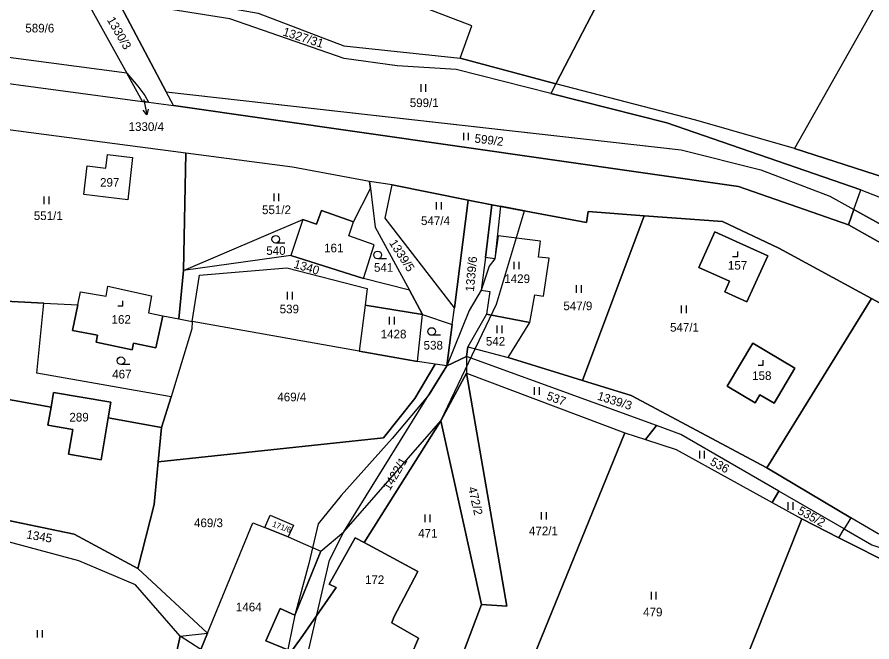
# Model space of a CAD drawing. Extents: x -588699 to -585793, y -1060280 to -1056731.
# Drawn here: x -586828.9 to -586660.9, y -1058673.3 to -1058550.5 of the extents above; entities that cross this region are included whole.
import ezdxf

# ---------------------------------------------------------------- set-up
doc = ezdxf.new("R2010")
doc.units = 0
for name, color, linetype in [('Druh pozemku', 7, 'Continuous'), ('Lesy', 7, 'Continuous'), ('Parcela nároku', 7, 'Continuous'), ('Parcelní číslo', 7, 'Continuous')]:
    doc.layers.add(name, color=color, linetype=linetype)

msp = doc.modelspace()

# ---------------------------------------------------------------- linework, layer by layer
at = {"layer": 'Druh pozemku'}
for p, q in [((-586749.55, -1058563.65), (-586749.55, -1058565.15)), ((-586748.53, -1058565.15), (-586748.53, -1058563.65)), ((-586741.18, -1058573.21), (-586741.18, -1058574.71)), ((-586740.16, -1058574.71), (-586740.16, -1058573.21)), ((-586778.45, -1058585.15), (-586778.45, -1058586.65)), ((-586777.43, -1058586.65), (-586777.43, -1058585.15)), ((-586823.62, -1058585.77), (-586823.62, -1058587.27)), ((-586822.59, -1058587.27), (-586822.59, -1058585.77)), ((-586746.52, -1058586.84), (-586746.52, -1058588.34)), ((-586745.49, -1058588.34), (-586745.49, -1058586.84)), ((-586776.29, -1058594.9), (-586778.04, -1058594.9)), ((-586756.27, -1058598), (-586758.02, -1058598)), ((-586731.24, -1058598.57), (-586731.24, -1058600.07)), ((-586730.21, -1058600.07), (-586730.21, -1058598.57)), ((-586719, -1058603.18), (-586719, -1058604.68)), ((-586717.97, -1058604.68), (-586717.97, -1058603.18)), ((-586775.81, -1058604.48), (-586775.81, -1058605.98)), ((-586774.79, -1058605.98), (-586774.79, -1058604.48)), ((-586698.37, -1058607.21), (-586698.37, -1058608.71)), ((-586697.34, -1058608.71), (-586697.34, -1058607.21)), ((-586755.75, -1058609.4), (-586755.75, -1058610.9)), ((-586754.72, -1058610.9), (-586754.72, -1058609.4)), ((-586734.62, -1058611.12), (-586734.62, -1058612.62)), ((-586733.59, -1058612.62), (-586733.59, -1058611.12)), ((-586745.65, -1058613.04), (-586747.4, -1058613.04)), ((-586806.72, -1058618.79), (-586808.47, -1058618.79)), ((-586727.26, -1058623.23), (-586727.26, -1058624.73)), ((-586726.23, -1058624.73), (-586726.23, -1058623.23)), ((-586694.82, -1058635.75), (-586694.82, -1058637.25)), ((-586693.8, -1058637.25), (-586693.8, -1058635.75)), ((-586677.44, -1058645.85), (-586677.44, -1058647.35)), ((-586676.42, -1058647.35), (-586676.42, -1058645.85)), ((-586748.76, -1058648.25), (-586748.76, -1058649.75)), ((-586747.73, -1058649.75), (-586747.73, -1058648.25)), ((-586725.87, -1058647.77), (-586725.87, -1058649.27)), ((-586724.84, -1058649.27), (-586724.84, -1058647.77)), ((-586704.3, -1058663.47), (-586704.3, -1058664.97)), ((-586703.28, -1058664.97), (-586703.28, -1058663.47)), ((-586824.9, -1058670.96), (-586824.9, -1058672.46)), ((-586823.88, -1058672.46), (-586823.88, -1058670.96))]:
    msp.add_line(p, q, dxfattribs=at)
for points in [[(-586688.29, -1058597.57), (-586687.29, -1058597.57), (-586687.29, -1058596.57)], [(-586809.11, -1058607.26), (-586808.11, -1058607.26), (-586808.11, -1058606.26)], [(-586683.27, -1058618.91), (-586682.27, -1058618.91), (-586682.27, -1058617.91)]]:
    msp.add_lwpolyline(points, dxfattribs=at)
for centre in [(-586778.04, -1058594.15), (-586758.02, -1058597.25), (-586747.4, -1058612.29), (-586808.47, -1058618.04)]:
    msp.add_circle(centre, 0.75, dxfattribs=at)
at = {"layer": 'Lesy'}
for p, q in [((-586808.99, -1058547.38), (-586799.56, -1058565.21)), ((-586799.56, -1058565.21), (-586748.98, -1058570.88)), ((-586748.98, -1058570.88), (-586698.41, -1058576.55)), ((-586698.41, -1058576.55), (-586682.76, -1058580.5)), ((-586682.76, -1058580.5), (-586669.18, -1058585.71)), ((-586669.18, -1058585.71), (-586664.46, -1058588.32)), ((-586664.46, -1058588.32), (-586623.04, -1058611.28)), ((-586817.65, -1058652.11), (-586851.48, -1058645.09)), ((-586674.68, -1058649.14), (-586694.07, -1058697.8)), ((-586667.41, -1058652.83), (-586674.68, -1058649.14)), ((-586805.15, -1058658.88), (-586817.65, -1058652.11)), ((-586656.24, -1058658.5), (-586667.41, -1058652.83)), ((-586791.48, -1058671.6), (-586805.15, -1058658.88)), ((-586799.98, -1058686.35), (-586796.81, -1058672.17)), ((-586796.81, -1058672.17), (-586791.48, -1058671.6))]:
    msp.add_line(p, q, dxfattribs=at)
msp.add_lwpolyline([(-586768.32, -1058678.54), (-586772.18, -1058677.61), (-586767.47, -1058657.22), (-586764.67, -1058651.64), (-586745.61, -1058629.88), (-586734.69, -1058606.92), (-586729.15, -1058588.58), (-586733.92, -1058587.68), (-586735.03, -1058597.99), (-586736.15, -1058599.47), (-586737.67, -1058604.17), (-586740.08, -1058608.18), (-586744.45, -1058619.04), (-586747.94, -1058624.66), (-586755.17, -1058633.29), (-586765.18, -1058644.52), (-586769.72, -1058650.09), (-586771.54, -1058657.92), (-586774.3, -1058668.05), (-586776.04, -1058676.69)], dxfattribs=at)
at = {"layer": 'Parcela nároku'}
for points in [[(-586465.07, -1058201.01), (-586462.81, -1058212.17), (-586445.25, -1058224.99), (-586469.35, -1058367.39), (-586494.03, -1058434.82), (-586515.59, -1058473.49), (-586537.48, -1058501.65), (-586550.1, -1058524), (-586565.09, -1058560.52), (-586647.87, -1058526.28), (-586676.13, -1058576.31), (-586695.54, -1058570.75), (-586723.01, -1058563.64), (-586690.86, -1058501.66), (-586638.81, -1058427.57), (-586625.18, -1058408.12), (-586613.79, -1058336.04), (-586618.19, -1058334.15), (-586615.1, -1058282.91), (-586614.12, -1058226.2), (-586599.85, -1058168.12)], [(-586934.89, -1058550.47), (-586933.62, -1058550.62), (-586874.68, -1058557.5), (-586872.37, -1058557.77), (-586854.02, -1058560.42), (-586804.23, -1058567.06), (-586803.05, -1058567.22), (-586798.16, -1058567.87), (-586687.14, -1058583.77), (-586665.54, -1058591.33), (-586602.99, -1058626.52)], [(-586618.94, -1058628.76), (-586660.99, -1058605.82), (-586679.22, -1058595.88), (-586690.29, -1058590.65), (-586705.65, -1058589.53), (-586716.68, -1058588.73), (-586716.99, -1058590.88), (-586735.61, -1058587.36), (-586740.23, -1058586.48), (-586755.16, -1058583.44), (-586759.61, -1058582.79), (-586774.79, -1058579.98), (-586795.7, -1058577.24), (-586856.59, -1058569.23), (-586909.75, -1058563.5), (-586913.94, -1058563.18), (-586935.4, -1058561.66), (-586937.84, -1058561.49), (-586942.57, -1058559.22), (-586946.78, -1058558.67)]]:
    msp.add_lwpolyline(points, dxfattribs=at)
for points in [[(-586698.57, -1058489.96), (-586674.92, -1058458.59), (-586651.91, -1058406.23), (-586620.38, -1058345.44), (-586618.19, -1058334.15), (-586613.79, -1058336.04), (-586625.18, -1058408.12), (-586638.81, -1058427.57), (-586690.86, -1058501.66), (-586723.01, -1058563.64), (-586741.83, -1058558.55), (-586739.53, -1058552.23), (-586753.05, -1058547), (-586757.7, -1058536.93), (-586767.21, -1058533.45), (-586771.86, -1058528.97), (-586755.85, -1058518.91), (-586720.86, -1058504.44)], [(-586799.85, -1058517.84), (-586802.95, -1058516.52), (-586804.09, -1058518.34), (-586814.11, -1058543.89), (-586781.49, -1058549.72), (-586764.67, -1058556.16), (-586741.83, -1058558.55), (-586739.53, -1058552.23), (-586753.05, -1058547), (-586757.7, -1058536.93), (-586767.21, -1058533.45), (-586771.86, -1058528.97), (-586775.6, -1058527.48)], [(-586871.4, -1058523.77), (-586875.35, -1058522.58), (-586869.14, -1058528.69), (-586874.19, -1058555.03), (-586862.54, -1058558.15), (-586854.02, -1058560.42), (-586804.23, -1058567.06), (-586807.28, -1058561.54), (-586832.56, -1058558.16), (-586845.52, -1058535.63), (-586863.45, -1058526.16)], [(-586565.09, -1058560.52), (-586647.87, -1058526.28), (-586676.13, -1058576.31), (-586614.58, -1058596.16), (-586607.11, -1058582.84), (-586599.58, -1058574.41), (-586596, -1058567.96), (-586573.24, -1058583.2)], [(-586845.52, -1058535.63), (-586838.02, -1058539.59), (-586814.5, -1058548.51), (-586807.28, -1058561.54), (-586832.56, -1058558.16)], [(-586814.11, -1058543.89), (-586781.49, -1058549.72), (-586764.67, -1058556.16), (-586741.83, -1058558.55), (-586723.01, -1058563.64), (-586723.97, -1058565.5), (-586742.59, -1058560.8), (-586754.19, -1058560.06), (-586764.62, -1058558.63), (-586787.05, -1058550.85), (-586808.99, -1058547.38)], [(-586799.56, -1058565.21), (-586808.99, -1058547.38), (-586814.5, -1058548.51), (-586807.28, -1058561.54), (-586805.12, -1058564.07), (-586803.77, -1058565.9), (-586803.05, -1058567.22), (-586798.16, -1058567.87)], [(-586764.62, -1058558.63), (-586787.05, -1058550.85), (-586808.99, -1058547.38), (-586799.56, -1058565.21), (-586698.41, -1058576.55), (-586682.76, -1058580.5), (-586669.18, -1058585.71), (-586664.46, -1058588.32), (-586663.07, -1058584.46), (-586701.18, -1058571.25), (-586723.97, -1058565.5), (-586742.59, -1058560.8), (-586754.19, -1058560.06)], [(-586807.28, -1058561.54), (-586805.12, -1058564.07), (-586803.77, -1058565.9), (-586803.05, -1058567.22), (-586804.23, -1058567.06)], [(-586695.54, -1058570.75), (-586723.01, -1058563.64), (-586723.97, -1058565.5), (-586701.18, -1058571.25), (-586663.07, -1058584.46), (-586649.29, -1058589.84), (-586616.31, -1058599.2), (-586600.16, -1058603.78), (-586584.46, -1058609.63), (-586574.88, -1058615.69), (-586569.97, -1058617.96), (-586565.57, -1058620.73), (-586521.47, -1058658.28), (-586520.5, -1058656.37), (-586561.85, -1058620.29), (-586566.13, -1058616.55), (-586566.86, -1058616.12), (-586567.54, -1058615.71), (-586570.85, -1058613.91), (-586582.12, -1058607.98), (-586593.62, -1058603.21), (-586614.58, -1058596.16), (-586676.13, -1058576.31)], [(-586669.18, -1058585.71), (-586664.46, -1058588.32), (-586665.54, -1058591.33), (-586687.14, -1058583.77), (-586798.16, -1058567.87), (-586799.56, -1058565.21), (-586698.41, -1058576.55), (-586682.76, -1058580.5)], [(-586848.05, -1058580.18), (-586854.38, -1058597.45), (-586849.98, -1058605.33), (-586823.61, -1058606.72), (-586816.91, -1058607.07), (-586816.4, -1058604.52), (-586811.36, -1058605.37), (-586811.07, -1058603.41), (-586802.46, -1058605.29), (-586803.06, -1058608.62), (-586800.23, -1058609.18), (-586797.12, -1058609.8), (-586796.17, -1058600.31), (-586795.7, -1058577.24), (-586856.59, -1058569.23), (-586845.36, -1058572.84)], [(-586806.18, -1058578.11), (-586807.14, -1058586.4), (-586815.79, -1058585.39), (-586815.13, -1058579.72), (-586811.45, -1058580.16), (-586811.13, -1058577.53)], [(-586815.13, -1058579.72), (-586811.45, -1058580.16), (-586811.13, -1058577.53), (-586806.18, -1058578.11), (-586807.14, -1058586.4), (-586815.79, -1058585.39)], [(-586759.61, -1058582.79), (-586774.79, -1058579.98), (-586795.7, -1058577.24), (-586796.17, -1058600.31), (-586772.71, -1058590.27), (-586770.05, -1058591.21), (-586769.05, -1058588.48), (-586762.75, -1058590.71), (-586759.45, -1058584.16)], [(-586755.16, -1058583.44), (-586759.61, -1058582.79), (-586759.45, -1058584.16), (-586758.54, -1058591.77), (-586751.79, -1058604.19), (-586749.19, -1058608.98), (-586743.37, -1058610.94), (-586742.95, -1058607.64), (-586756.53, -1058590.02)], [(-586756.53, -1058590.02), (-586755.16, -1058583.44), (-586740.23, -1058586.48), (-586742.95, -1058607.64)], [(-586760.82, -1058601.89), (-586758.69, -1058595.23), (-586763.68, -1058593.46), (-586762.75, -1058590.71), (-586759.45, -1058584.16), (-586758.54, -1058591.77), (-586751.79, -1058604.19)], [(-586649.29, -1058589.84), (-586616.31, -1058599.2), (-586623.04, -1058611.28), (-586664.46, -1058588.32), (-586663.07, -1058584.46)], [(-586742.95, -1058607.64), (-586740.23, -1058586.48), (-586735.61, -1058587.36), (-586736.87, -1058597.72), (-586737.67, -1058604.17), (-586735.99, -1058604.42), (-586736.65, -1058608.87), (-586740.28, -1058615.3), (-586740.58, -1058617.2), (-586744.45, -1058619.04), (-586743.37, -1058610.94)], [(-586769.05, -1058588.48), (-586770.05, -1058591.21), (-586772.71, -1058590.27), (-586775.09, -1058597.32), (-586760.82, -1058601.89), (-586758.69, -1058595.23), (-586763.68, -1058593.46), (-586762.75, -1058590.71)], [(-586725.43, -1058605.36), (-586724.33, -1058597.89), (-586726.41, -1058597.67), (-586726.04, -1058594.56), (-586734.37, -1058593.49), (-586735.03, -1058597.99), (-586736.87, -1058597.72), (-586735.61, -1058587.36), (-586716.99, -1058590.88), (-586716.68, -1058588.73), (-586705.65, -1058589.53), (-586717.75, -1058621.93), (-586732.41, -1058617.37), (-586728.1, -1058610.55), (-586727.15, -1058605.11)], [(-586597.95, -1058625.16), (-586584.01, -1058632.77), (-586561.96, -1058648.55), (-586562.62, -1058649.44), (-586575.18, -1058640.72), (-586602.99, -1058626.52), (-586665.54, -1058591.33), (-586664.46, -1058588.32), (-586623.04, -1058611.28), (-586607.59, -1058619.84), (-586605.96, -1058620.74), (-586600.89, -1058623.54)], [(-586796.17, -1058600.31), (-586772.71, -1058590.27), (-586775.09, -1058597.32)], [(-586690.29, -1058590.65), (-586679.22, -1058595.88), (-586660.99, -1058605.82), (-586681.54, -1058639.09), (-586708.24, -1058624.88), (-586717.75, -1058621.93), (-586705.65, -1058589.53)], [(-586735.03, -1058597.99), (-586736.87, -1058597.72), (-586737.67, -1058604.17), (-586735.99, -1058604.42), (-586736.65, -1058608.87), (-586728.1, -1058610.55), (-586727.15, -1058605.11), (-586725.43, -1058605.36), (-586724.33, -1058597.89), (-586726.41, -1058597.67), (-586726.04, -1058594.56), (-586734.37, -1058593.49)], [(-586689.84, -1058604.5), (-586688.89, -1058602.39), (-586694.92, -1058599.68), (-586691.79, -1058592.73), (-586681.39, -1058597.39), (-586685.48, -1058606.46)], [(-586694.92, -1058599.68), (-586688.89, -1058602.39), (-586689.84, -1058604.5), (-586685.48, -1058606.46), (-586681.39, -1058597.39), (-586691.79, -1058592.73)], [(-586775.09, -1058597.32), (-586796.17, -1058600.31), (-586797.12, -1058609.8), (-586794.44, -1058610.33), (-586793.06, -1058601.19), (-586775.86, -1058599.8), (-586760.09, -1058603.85), (-586760.51, -1058607.14), (-586749.19, -1058608.98), (-586751.79, -1058604.19), (-586760.82, -1058601.89)], [(-586793.06, -1058601.19), (-586775.86, -1058599.8), (-586760.09, -1058603.85), (-586760.51, -1058607.14), (-586761.66, -1058616.17), (-586794.44, -1058610.33)], [(-586811.36, -1058605.37), (-586811.07, -1058603.41), (-586802.46, -1058605.29), (-586803.06, -1058608.62), (-586800.23, -1058609.18), (-586801.59, -1058615.49), (-586805.98, -1058614.57), (-586806.25, -1058615.92), (-586813.35, -1058614.38), (-586813.07, -1058613.02), (-586817.98, -1058612.11), (-586816.91, -1058607.07), (-586816.4, -1058604.52)], [(-586823.61, -1058606.72), (-586849.98, -1058605.33), (-586851.42, -1058615.61), (-586851.29, -1058621.89), (-586822.19, -1058627.19), (-586821.69, -1058624.31), (-586810.47, -1058626.19), (-586810.97, -1058629.24), (-586800.47, -1058631.15), (-586798.62, -1058625.12), (-586825.01, -1058620.48)], [(-586797.12, -1058609.8), (-586794.44, -1058610.33), (-586794.51, -1058611.77), (-586798.62, -1058625.12), (-586825.01, -1058620.48), (-586823.61, -1058606.72), (-586816.91, -1058607.07), (-586817.98, -1058612.11), (-586813.07, -1058613.02), (-586813.35, -1058614.38), (-586806.25, -1058615.92), (-586805.98, -1058614.57), (-586801.59, -1058615.49), (-586800.23, -1058609.18)], [(-586760.51, -1058607.14), (-586761.66, -1058616.17), (-586750.18, -1058618.21), (-586749.19, -1058608.98)], [(-586681.54, -1058639.09), (-586660.99, -1058605.82), (-586618.94, -1058628.76), (-586637.88, -1058658.21), (-586659.72, -1058652.09), (-586665.04, -1058648.92)], [(-586750.18, -1058618.21), (-586749.19, -1058608.98), (-586743.37, -1058610.94), (-586744.45, -1058619.04), (-586746.74, -1058618.71)], [(-586736.65, -1058608.87), (-586740.28, -1058615.3), (-586732.41, -1058617.37), (-586728.1, -1058610.55)], [(-586746.74, -1058618.71), (-586750.18, -1058618.21), (-586761.66, -1058616.17), (-586794.44, -1058610.33), (-586794.51, -1058611.77), (-586798.62, -1058625.12), (-586800.47, -1058631.15), (-586801.14, -1058637.92), (-586756.88, -1058633.16), (-586750.74, -1058625.45)], [(-586681.54, -1058639.09), (-586665.04, -1058648.92), (-586666.36, -1058651.1), (-586679.21, -1058643.65), (-586698.43, -1058632.52), (-586703.25, -1058630.77), (-586740.58, -1058617.2), (-586740.28, -1058615.3), (-586732.41, -1058617.37), (-586717.75, -1058621.93), (-586708.24, -1058624.88)], [(-586689.33, -1058623.05), (-586684.33, -1058614.61), (-586676.03, -1058619.48), (-586680.12, -1058626.38), (-586682.92, -1058624.73), (-586683.85, -1058626.3)], [(-586680.12, -1058626.38), (-586676.03, -1058619.48), (-586684.33, -1058614.61), (-586689.33, -1058623.05), (-586683.85, -1058626.3), (-586682.92, -1058624.73)], [(-586740.58, -1058617.2), (-586740.56, -1058620.49), (-586745.61, -1058629.88), (-586760.71, -1058653.77), (-586762.47, -1058652.82), (-586767.54, -1058661.93), (-586766.21, -1058662.62), (-586772.73, -1058672.04), (-586776.04, -1058676.69), (-586775.34, -1058674.97), (-586779.97, -1058673.07), (-586777.15, -1058666.75), (-586774.3, -1058668.05), (-586769.19, -1058655.47), (-586764.67, -1058651.64), (-586744.45, -1058619.04)], [(-586703.25, -1058630.77), (-586740.58, -1058617.2), (-586740.56, -1058620.49), (-586709.46, -1058632.19), (-586705.4, -1058633.51)], [(-586750.74, -1058625.45), (-586756.88, -1058633.16), (-586801.14, -1058637.92), (-586801.97, -1058646.29), (-586805.15, -1058658.88), (-586791.48, -1058671.6), (-586782.58, -1058649.89), (-586780.19, -1058650.83), (-586779.13, -1058648.42), (-586774.55, -1058650.35), (-586775.59, -1058652.67), (-586772.21, -1058654.14), (-586769.19, -1058655.47), (-586764.67, -1058651.64), (-586744.45, -1058619.04), (-586746.74, -1058618.71)], [(-586745.61, -1058629.88), (-586740.56, -1058620.49), (-586732.66, -1058666.25), (-586737.6, -1058665.97)], [(-586744.08, -1058683.08), (-586737.6, -1058665.97), (-586732.66, -1058666.25), (-586740.56, -1058620.49), (-586709.46, -1058632.19), (-586731.52, -1058686.37)], [(-586822.19, -1058627.19), (-586851.29, -1058621.89), (-586851.01, -1058642.14), (-586851.48, -1058645.09), (-586817.65, -1058652.11), (-586805.15, -1058658.88), (-586801.97, -1058646.29), (-586801.14, -1058637.92), (-586800.47, -1058631.15), (-586810.97, -1058629.24), (-586812.33, -1058637.49), (-586818.79, -1058636.38), (-586817.95, -1058631.53), (-586822.8, -1058630.72)], [(-586822.19, -1058627.19), (-586822.8, -1058630.72), (-586817.95, -1058631.53), (-586818.79, -1058636.38), (-586812.33, -1058637.49), (-586810.97, -1058629.24), (-586810.47, -1058626.19), (-586821.69, -1058624.31)], [(-586760.71, -1058653.77), (-586745.61, -1058629.88), (-586737.6, -1058665.97), (-586744.08, -1058683.08), (-586754.43, -1058685.69), (-586762.04, -1058681.65), (-586761.21, -1058680.01), (-586754.5, -1058683.18), (-586750, -1058672.54), (-586755.27, -1058669.57), (-586754.82, -1058668.46), (-586750.12, -1058659.46)], [(-586703.25, -1058630.77), (-586705.4, -1058633.51), (-586699.35, -1058635.49), (-586680.49, -1058645.92), (-586679.21, -1058643.65), (-586698.43, -1058632.52)], [(-586705.4, -1058633.51), (-586699.35, -1058635.49), (-586680.49, -1058645.92), (-586674.68, -1058649.14), (-586694.07, -1058697.8), (-586731.52, -1058686.37), (-586709.46, -1058632.19)], [(-586666.36, -1058651.1), (-586679.21, -1058643.65), (-586680.49, -1058645.92), (-586674.68, -1058649.14), (-586667.41, -1058652.83)], [(-586851.48, -1058645.09), (-586817.65, -1058652.11), (-586805.15, -1058658.88), (-586791.48, -1058671.6), (-586792.77, -1058674.76), (-586796.81, -1058672.17), (-586805.63, -1058662.11), (-586816.72, -1058657.34), (-586840.89, -1058650.86), (-586852.11, -1058648.46)], [(-586780.19, -1058650.83), (-586779.13, -1058648.42), (-586774.55, -1058650.35), (-586775.59, -1058652.67)], [(-586656.24, -1058658.5), (-586648.82, -1058664.43), (-586635.45, -1058676.95), (-586627.51, -1058684.38), (-586620.49, -1058689.29), (-586605.29, -1058703.42), (-586575.6, -1058727.47), (-586587.34, -1058735.8), (-586608.24, -1058752.75), (-586626.83, -1058736.19), (-586643.18, -1058723.44), (-586668.27, -1058711.07), (-586694.07, -1058697.8), (-586674.68, -1058649.14), (-586667.41, -1058652.83)], [(-586665.04, -1058648.92), (-586666.36, -1058651.1), (-586660.95, -1058654.23), (-586636.48, -1058662.22), (-586632.69, -1058670.06), (-586632.17, -1058672.66), (-586629.39, -1058669.03), (-586637.88, -1058658.21), (-586659.72, -1058652.09)], [(-586805.63, -1058662.11), (-586816.72, -1058657.34), (-586840.89, -1058650.86), (-586854.39, -1058683.44), (-586852.02, -1058685.29), (-586820.88, -1058699.32), (-586805.39, -1058705.78), (-586803.87, -1058706.44), (-586802.96, -1058699.63), (-586799.98, -1058686.35), (-586796.81, -1058672.17)], [(-586772.21, -1058654.14), (-586769.19, -1058655.47), (-586774.3, -1058668.05), (-586777.15, -1058666.75), (-586779.97, -1058673.07), (-586775.34, -1058674.97), (-586776.04, -1058676.69), (-586776.99, -1058679.01), (-586777.74, -1058680.85), (-586792.77, -1058674.76), (-586791.48, -1058671.6), (-586782.58, -1058649.89), (-586780.19, -1058650.83), (-586775.59, -1058652.67)], [(-586632.69, -1058670.06), (-586632.17, -1058672.66), (-586635.45, -1058676.95), (-586648.82, -1058664.43), (-586656.24, -1058658.5), (-586667.41, -1058652.83), (-586666.36, -1058651.1), (-586660.95, -1058654.23), (-586636.48, -1058662.22)], [(-586767.54, -1058661.93), (-586762.47, -1058652.82), (-586760.71, -1058653.77), (-586750.12, -1058659.46), (-586754.82, -1058668.46), (-586755.27, -1058669.57), (-586750, -1058672.54), (-586754.5, -1058683.18), (-586761.21, -1058680.01), (-586762.04, -1058681.65), (-586768.32, -1058678.54), (-586776.04, -1058676.69), (-586772.73, -1058672.04), (-586766.21, -1058662.62)], [(-586796.81, -1058672.17), (-586799.98, -1058686.35), (-586797.87, -1058687.2), (-586792.77, -1058674.76)]]:
    msp.add_lwpolyline(points, close=True, dxfattribs=at)
at = {"layer": 'Parcelní číslo'}
msp.add_line((-586803.95, -1058566.74), (-586803.41, -1058569.69), dxfattribs=at)
msp.add_lwpolyline([(-586803.1, -1058568.62), (-586803.41, -1058569.69), (-586804.08, -1058568.8)], dxfattribs=at)

# ---------------------------------------------------------------- texts
at = {"layer": 'Parcela nároku'}
for s, height, p in [('589/6', 1.7, (-586827.25, -1058553.51)), ('1330/4', 0.1, (-586804.16, -1058566.74)), ('599/1', 1.7, (-586751.72, -1058568.18)), ('297', 1.7, (-586812.57, -1058583.83)), ('551/1', 1.7, (-586825.59, -1058590.38)), ('551/2', 1.7, (-586780.75, -1058589.22)), ('547/4', 1.7, (-586749.51, -1058591.37)), ('540', 1.7, (-586779.91, -1058597.23)), ('161', 1.7, (-586768.55, -1058596.73)), ('541', 1.7, (-586758.75, -1058600.55)), ('157', 1.7, (-586689.21, -1058600.13)), ('1429', 1.7, (-586733.15, -1058602.77)), ('539', 1.7, (-586777.28, -1058608.72)), ('547/9', 1.7, (-586721.54, -1058608.1)), ('162', 1.7, (-586810.31, -1058610.77)), ('547/1', 1.7, (-586700.58, -1058612.32)), ('1428', 1.7, (-586757.43, -1058613.65)), ('542', 1.7, (-586736.76, -1058615.06)), ('538', 1.7, (-586749, -1058615.84)), ('467', 1.7, (-586810.18, -1058621.52)), ('158', 1.7, (-586684.45, -1058621.82)), ('469/4', 1.7, (-586777.74, -1058626.01)), ('289', 1.7, (-586818.59, -1058629.98)), ('469/3', 1.7, (-586794.11, -1058650.74)), ('472/1', 1.7, (-586728.3, -1058652.33)), ('471', 1.7, (-586750.06, -1058652.8)), ('172', 1.7, (-586760.52, -1058661.93)), ('1464', 1.7, (-586785.88, -1058667.29)), ('479', 1.7, (-586705.86, -1058668.28))]:
    msp.add_text(s, height=height, dxfattribs=at).set_placement(p)
for s, height, rotation, p in [('1330/3', 1.7, 300.0686, (-586811.27, -1058551.04)), ('1327/31', 1.7, 342.2324, (-586776.8, -1058554.07)), ('599/2', 1.7, 352.8814, (-586739.07, -1058575.13)), ('1339/5', 1.7, 302.8799, (-586755.85, -1058594.88)), ('1340', 1.7, 343.425, (-586774.64, -1058599.73)), ('1339/6', 1.7, 84.6042, (-586739.12, -1058604.53)), ('537', 1.7, 339.6826, (-586725, -1058625.61)), ('1339/3', 1.7, 342.5117, (-586715.01, -1058625.65)), ('1422/1', 1.7, 59.7364, (-586755.65, -1058643.7)), ('536', 1.7, 330.9494, (-586692.88, -1058638.38)), ('472/2', 1.7, 282.9124, (-586740.28, -1058643)), ('535/2', 1.7, 330.8462, (-586675.67, -1058648.01)), ('171/6', 1.14, 339.9921, (-586778.84, -1058650.59)), ('1345', 1.7, 350.1813, (-586827.13, -1058652.95))]:
    msp.add_text(s, height=height, rotation=rotation, dxfattribs=at).set_placement(p)
at = {"layer": 'Parcelní číslo'}
msp.add_text('1330/4', height=1.7, dxfattribs=at).set_placement((-586806.96, -1058572.87))

doc.saveas('drawing.dxf')
